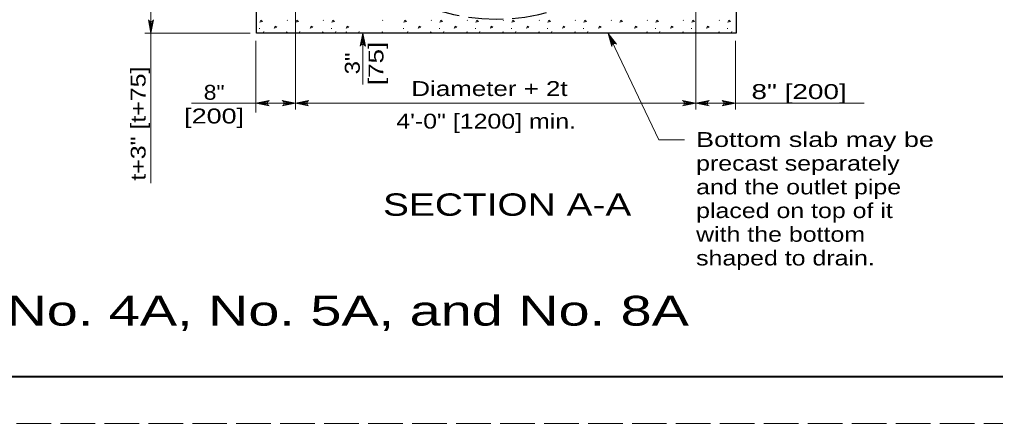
# Model space of a CAD drawing. Extents: x 1073.4 to 1107.4, y 719.4 to 741.4.
# Drawn here: x 1084.72 to 1095.2, y 719.35 to 723.69 of the extents above; entities that cross this region are included whole.
import ezdxf
from ezdxf.enums import TextEntityAlignment as Align

# ---------------------------------------------------------------- set-up
doc = ezdxf.new("R2010")
doc.units = 0
doc.header["$LTSCALE"] = 0.062
doc.linetypes.add('LONG_DASHED', pattern=[7.5, 6, -1.5])
doc.layers.add('1', color=7, linetype='Continuous', lineweight=13)

msp = doc.modelspace()

# ---------------------------------------------------------------- linework, layer by layer
at = {"layer": '1', "lineweight": 25}
msp.add_line((1092.41392, 724.97575), (1092.41392, 723.54533), dxfattribs=at)
at = {"layer": '1'}
for p, q in [((1086.1335, 724.04508), (1086.1335, 721.93425)), ((1087.68458, 722.7255), (1087.68458, 723.93633)), ((1091.98275, 722.7255), (1091.98275, 723.96242)), ((1087.59442, 723.68492), (1087.59792, 723.67958)), ((1087.98092, 723.68492), (1087.9845, 723.67958)), ((1088.6185, 723.68492), (1088.62208, 723.67958)), ((1089.14075, 723.68492), (1089.14425, 723.67958)), ((1089.52725, 723.68492), (1089.53092, 723.67958)), ((1089.91392, 723.68492), (1089.9175, 723.67958)), ((1090.3005, 723.68492), (1090.30408, 723.67958)), ((1090.68708, 723.68492), (1090.69058, 723.67958)), ((1091.07375, 723.68492), (1091.07725, 723.67958)), ((1091.46025, 723.68492), (1091.46383, 723.67958)), ((1091.84692, 723.68492), (1091.85042, 723.67958)), ((1092.23342, 723.68492), (1092.237, 723.67958)), ((1086.11558, 723.6735), (1086.1335, 723.54533)), ((1086.12442, 723.66917), (1086.1335, 723.54533)), ((1086.15325, 723.67508), (1086.1335, 723.54533)), ((1086.145, 723.67008), (1086.1335, 723.54533)), ((1086.1335, 723.66783), (1086.1335, 723.54533)), ((1087.29758, 723.59975), (1087.29842, 723.59175)), ((1087.68408, 723.59975), (1087.685, 723.59175)), ((1088.07075, 723.59975), (1088.07158, 723.59175)), ((1088.84392, 723.59975), (1088.84475, 723.59175)), ((1089.2305, 723.59975), (1089.23142, 723.59175)), ((1089.61708, 723.59975), (1089.61792, 723.59175)), ((1090.00367, 723.59975), (1090.00458, 723.59175)), ((1090.39025, 723.59975), (1090.39108, 723.59175)), ((1090.77692, 723.59975), (1090.77775, 723.59175)), ((1091.55, 723.59975), (1091.55092, 723.59175)), ((1091.93658, 723.59975), (1091.9375, 723.59175)), ((1092.32325, 723.59975), (1092.32408, 723.59175)), ((1086.06683, 723.54533), (1087.1995, 723.54533)), ((1087.33967, 723.55267), (1087.34325, 723.56067)), ((1087.72625, 723.55267), (1087.72983, 723.56067)), ((1088.11283, 723.55267), (1088.11633, 723.56067)), ((1088.36375, 723.55267), (1088.36733, 723.56067)), ((1088.38658, 723.41567), (1088.40642, 723.54533)), ((1088.39492, 723.4205), (1088.40642, 723.54533)), ((1088.40642, 723.42275), (1088.40642, 723.54533)), ((1088.4155, 723.4215), (1088.40642, 723.54533)), ((1088.42433, 723.41708), (1088.40642, 723.54533)), ((1088.40642, 723.54533), (1088.40642, 722.99383)), ((1088.886, 723.55267), (1088.88958, 723.56067)), ((1089.27258, 723.55267), (1089.27617, 723.56067)), ((1089.65925, 723.55267), (1089.66267, 723.56067)), ((1090.04583, 723.55267), (1090.04933, 723.56067)), ((1090.43233, 723.55267), (1090.43592, 723.56067)), ((1090.81892, 723.55267), (1090.8225, 723.56067)), ((1091.09617, 723.43017), (1091.04225, 723.54008)), ((1091.08692, 723.423), (1091.04225, 723.54008)), ((1091.08158, 723.41492), (1091.04225, 723.54008)), ((1091.105, 723.433), (1091.04225, 723.54008)), ((1091.11483, 723.433), (1091.04225, 723.54008)), ((1091.04225, 723.54008), (1091.58417, 722.4)), ((1091.59217, 723.55267), (1091.59567, 723.56067)), ((1091.97867, 723.55267), (1091.98225, 723.56067)), ((1092.36525, 723.55267), (1092.36883, 723.56067)), ((1087.25975, 722.69217), (1087.25975, 723.46208)), ((1092.40758, 722.7255), (1092.40758, 723.46208)), ((1086.56758, 722.79217), (1087.65958, 722.79217)), ((1087.38792, 722.81008), (1087.25975, 722.79217)), ((1087.38358, 722.80117), (1087.25975, 722.79217)), ((1087.38225, 722.79217), (1087.25975, 722.79217)), ((1087.38458, 722.78067), (1087.25975, 722.79217)), ((1087.3895, 722.77233), (1087.25975, 722.79217)), ((1087.55492, 722.77233), (1087.68458, 722.79217)), ((1087.55633, 722.81008), (1087.68458, 722.79217)), ((1087.55975, 722.78067), (1087.68458, 722.79217)), ((1087.56075, 722.80117), (1087.68458, 722.79217)), ((1087.562, 722.79217), (1087.68458, 722.79217)), ((1087.81275, 722.81008), (1087.68458, 722.79217)), ((1087.80842, 722.80117), (1087.68458, 722.79217)), ((1087.80708, 722.79217), (1087.68458, 722.79217)), ((1087.80933, 722.78067), (1087.68458, 722.79217)), ((1087.81425, 722.77233), (1087.68458, 722.79217)), ((1091.853, 722.77233), (1091.98275, 722.79217)), ((1091.85458, 722.81008), (1091.98275, 722.79217)), ((1091.85792, 722.78067), (1091.98275, 722.79217)), ((1091.85892, 722.80117), (1091.98275, 722.79217)), ((1091.86025, 722.79217), (1091.98275, 722.79217)), ((1092.11092, 722.81008), (1091.98275, 722.79217)), ((1092.10658, 722.80117), (1091.98275, 722.79217)), ((1092.10525, 722.79217), (1091.98275, 722.79217)), ((1092.10758, 722.78067), (1091.98275, 722.79217)), ((1092.1125, 722.77233), (1091.98275, 722.79217)), ((1092.27783, 722.77233), (1092.40758, 722.79217)), ((1092.27933, 722.81008), (1092.40758, 722.79217)), ((1092.28275, 722.78067), (1092.40758, 722.79217)), ((1092.28367, 722.80117), (1092.40758, 722.79217)), ((1092.285, 722.79217), (1092.40758, 722.79217)), ((1091.58417, 722.4), (1091.86008, 722.4))]:
    msp.add_line(p, q, dxfattribs=at)
at = {"layer": '1', "linetype": 'LONG_DASHED'}
msp.add_lwpolyline([(1073.36142, 719.35408), (1107.36142, 719.35408), (1107.36142, 741.35408), (1073.36142, 741.35408)], close=True, dxfattribs=at)
at = {"layer": '1', "lineweight": 25}
for points in [[(1106.86142, 719.85408), (1075.36142, 719.85408), (1075.36142, 740.85408)], [(1092.41392, 723.54533), (1087.26608, 723.54533), (1087.26608, 728.54242)]]:
    msp.add_lwpolyline(points, dxfattribs=at)
at = {"layer": '1', "lineweight": 40}
msp.add_lwpolyline([(1075.36142, 740.85408), (1106.86142, 740.85408), (1106.86142, 719.85408), (1075.36142, 719.85408)], close=True, dxfattribs=at)
msp.add_lwpolyline([(1075.36142, 740.85408), (1106.86142, 740.85408), (1106.86142, 719.85408), (1075.36142, 719.85408)], close=True, dxfattribs=at)
at = {"layer": '1'}
for points in [[(1086.16183, 723.68692), (1086.1335, 723.54533), (1086.10517, 723.68692)], [(1087.58792, 723.54533), (1087.58958, 723.55775), (1087.60167, 723.54533)], [(1087.97442, 723.54533), (1087.97617, 723.55775), (1087.98825, 723.54533)], [(1088.22542, 723.54533), (1088.22717, 723.55775), (1088.23925, 723.54533)], [(1088.37817, 723.40375), (1088.40642, 723.54533), (1088.43475, 723.40375)], [(1088.61192, 723.54533), (1088.61367, 723.55775), (1088.62575, 723.54533)], [(1089.13425, 723.54533), (1089.13592, 723.55775), (1089.148, 723.54533)], [(1089.52075, 723.54533), (1089.5225, 723.55775), (1089.53458, 723.54533)], [(1089.90742, 723.54533), (1089.90917, 723.55775), (1089.92125, 723.54533)], [(1090.29392, 723.54533), (1090.29567, 723.55775), (1090.30775, 723.54533)], [(1090.68058, 723.54533), (1090.68225, 723.55775), (1090.69433, 723.54533)], [(1091.07917, 723.40058), (1091.04225, 723.54008), (1091.13, 723.4255)], [(1091.45375, 723.54533), (1091.4555, 723.55775), (1091.46758, 723.54533)], [(1091.84033, 723.54533), (1091.84208, 723.55775), (1091.85417, 723.54533)], [(1092.22692, 723.54533), (1092.22858, 723.55775), (1092.24067, 723.54533)], [(1087.40133, 722.76383), (1087.25975, 722.79217), (1087.40133, 722.82042)], [(1087.54292, 722.76383), (1087.68458, 722.79217), (1087.54292, 722.82042)], [(1087.65958, 722.79217), (1091.98275, 722.79217), (1093.79017, 722.79217)], [(1087.82617, 722.76383), (1087.68458, 722.79217), (1087.82617, 722.82042)], [(1091.84117, 722.76383), (1091.98275, 722.79217), (1091.84117, 722.82042)], [(1092.12433, 722.76383), (1091.98275, 722.79217), (1092.12433, 722.82042)], [(1092.26592, 722.76383), (1092.40758, 722.79217), (1092.26592, 722.82042)]]:
    msp.add_lwpolyline(points, dxfattribs=at)
for points in [[(1087.301, 723.66175), (1087.31158, 723.684), (1087.32942, 723.67075)], [(1087.68758, 723.66175), (1087.69825, 723.684), (1087.71592, 723.67075)], [(1088.07425, 723.66175), (1088.08492, 723.684), (1088.10258, 723.67075)], [(1088.84733, 723.66175), (1088.858, 723.684), (1088.87575, 723.67075)], [(1089.23392, 723.66175), (1089.24458, 723.684), (1089.26233, 723.67075)], [(1089.62058, 723.66175), (1089.63125, 723.684), (1089.64892, 723.67075)], [(1090.00717, 723.66175), (1090.01775, 723.684), (1090.03558, 723.67075)], [(1090.39367, 723.66175), (1090.40433, 723.684), (1090.42208, 723.67075)], [(1090.78033, 723.66175), (1090.79092, 723.684), (1090.80867, 723.67075)], [(1091.16692, 723.66175), (1091.17758, 723.684), (1091.19525, 723.67075)], [(1091.5535, 723.66175), (1091.56417, 723.684), (1091.58192, 723.67075)], [(1091.94, 723.66175), (1091.95067, 723.684), (1091.96842, 723.67075)], [(1092.32667, 723.66175), (1092.33733, 723.684), (1092.355, 723.67075)], [(1087.457, 723.59842), (1087.46758, 723.62058), (1087.48542, 723.60725)], [(1087.84358, 723.59842), (1087.85425, 723.62058), (1087.87192, 723.60725)], [(1088.23025, 723.59842), (1088.24083, 723.62058), (1088.25858, 723.60725)], [(1089.00333, 723.59842), (1089.014, 723.62058), (1089.03175, 723.60725)], [(1089.38992, 723.59842), (1089.40058, 723.62058), (1089.41833, 723.60725)], [(1089.77658, 723.59842), (1089.78725, 723.62058), (1089.80492, 723.60725)], [(1090.16308, 723.59842), (1090.17375, 723.62058), (1090.19158, 723.60725)], [(1090.54967, 723.59842), (1090.56033, 723.62058), (1090.57808, 723.60725)], [(1090.93625, 723.59842), (1090.94692, 723.62058), (1090.96467, 723.60725)], [(1091.32292, 723.59842), (1091.33358, 723.62058), (1091.35125, 723.60725)], [(1091.7095, 723.59842), (1091.72008, 723.62058), (1091.73792, 723.60725)], [(1092.096, 723.59842), (1092.10667, 723.62058), (1092.12442, 723.60725)]]:
    msp.add_lwpolyline(points, close=True, dxfattribs=at)
for centre, start, end in [((1086.13344, 723.69837), 202.08782, 337.91395), ((1088.40648, 723.3923), 22.08782, 157.91395), ((1091.10969, 723.40277), 48.24096, 184.06709), ((1087.41281, 722.79218), 112.08782, 247.91395), ((1087.53154, 722.79218), 292.08605, 67.91218), ((1087.83761, 722.79218), 112.08782, 247.91395), ((1091.82971, 722.79218), 292.08605, 67.91218), ((1092.13578, 722.79218), 112.08782, 247.91395), ((1092.25451, 722.79218), 292.08605, 67.91218)]:
    msp.add_arc(centre, 0.03056, start, end, dxfattribs=at)
at = {"layer": '1', "linetype": 'LONG_DASHED', "lineweight": 25}
msp.add_ellipse((1089.8401, 725.84401), major_axis=(2.14899, 0), ratio=0.999895, start_param=4.13375193, end_param=5.29102604, dxfattribs=at)

# ---------------------------------------------------------------- texts
at = {"layer": '1'}
for s, width, p in [('[75]', 1.3, (1088.629, 723.21954)), ('3"', 1.2, (1088.37458, 723.21958))]:
    msp.add_text(s, height=0.16, rotation=90, dxfattribs=dict(at, width=width)).set_placement(p, align=Align.CENTER)
at = {"layer": '1', "width": 1.25}
msp.add_text('t+3" [t+75]', height=0.16, rotation=90, dxfattribs=at).set_placement((1086.07592, 721.96083))
at = {"layer": '1'}
for s, width, p in [('8"', 1.15, (1086.81146, 722.8295)), ('Diameter + 2t', 1.3, (1089.76729, 722.86958)), ('[200]', 1.35, (1086.81154, 722.57508)), ('4\'-0" [1200] min.', 1.25, (1089.73183, 722.51983))]:
    msp.add_text(s, height=0.16, dxfattribs=dict(at, width=width)).set_placement(p, align=Align.CENTER)
for s, height, width, p in [('8" [200]', 0.16, 1.4, (1092.58, 722.83733)), ('Bottom slab may be', 0.16, 1.35, (1091.98567, 722.32283)), ('precast separately', 0.16, 1.25, (1091.98567, 722.06842)), ('and the outlet pipe', 0.16, 1.25, (1091.98567, 721.814)), ('SECTION A-A', 0.24, 1.3, (1088.62442, 721.58417)), ('placed on top of it', 0.16, 1.25, (1091.98567, 721.55958)), ('with the bottom', 0.16, 1.25, (1091.98567, 721.30517)), ('shaped to drain.', 0.16, 1.25, (1091.98567, 721.05075)), ('CATCH BASINS No. 4A, No. 5A, and No. 8A', 0.32, 1.4, (1079.988, 720.40475))]:
    msp.add_text(s, height=height, dxfattribs=dict(at, width=width)).set_placement(p)

doc.saveas('drawing.dxf')
